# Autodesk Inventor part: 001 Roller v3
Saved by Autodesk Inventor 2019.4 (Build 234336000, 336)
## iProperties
Created: 2020-06
Part Number: 001 Roller v3
Material: Generic
Document SubType Name: Modeling
Designer: Administrator
Density: 1 g/cm^3
Appearance: Default
Title: 001 Roller v3
Author: Administrator
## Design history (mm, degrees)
